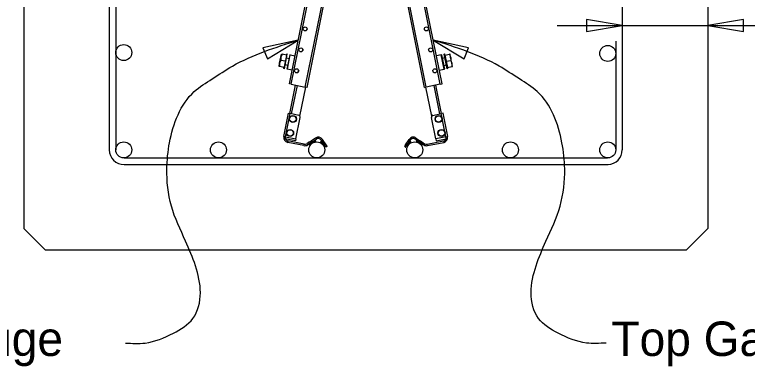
# Model space of a CAD drawing. Extents: x 0 to 36.1, y -3.7 to 15.
# Drawn here: x 2.266 to 4.409, y 2.071 to 3.1 of the extents above; entities that cross this region are included whole.
import ezdxf

# ---------------------------------------------------------------- set-up
doc = ezdxf.new("R2010")
doc.units = 0
for name, color, linetype in [('Dimension', 7, 'Continuous'), ('Leader', 7, 'Continuous'), ('Miscellaneous', 7, 'Continuous'), ('PileConc', 7, 'Continuous'), ('PrestressSteel', 7, 'Continuous')]:
    doc.layers.add(name, color=color, linetype=linetype)

msp = doc.modelspace()

# ---------------------------------------------------------------- linework, layer by layer
at = {"layer": 'Dimension'}
for p, q in [((3.8524, 3.0685), (4.043, 3.0685)), ((4.043, 3.0685), (4.293, 3.0685)), ((4.293, 3.0685), (5.1697, 3.0685))]:
    msp.add_line(p, q, dxfattribs=at)
for points in [[(4.043, 3.0685), (3.9389, 3.0861), (3.9389, 3.0508)], [(4.293, 3.0685), (4.3972, 3.0508), (4.3972, 3.0861)], [(3.0957, 3.0249), (2.9923, 3.0032), (3.0052, 2.9704)], [(3.4904, 3.0249), (3.5809, 2.9704), (3.5938, 3.0032)]]:
    msp.add_lwpolyline(points, close=True, dxfattribs=at)
at = {"layer": 'Leader'}
for points in [[(2.5903, 2.1388), (2.6477, 2.1388), (2.7303, 2.1675), (2.7877, 2.2106), (2.8093, 2.2859), (2.7949, 2.3649), (2.7662, 2.4367), (2.7246, 2.5398), (2.7114, 2.6484), (2.7193, 2.7252), (2.7913, 2.8747), (2.8439, 2.912), (2.903, 2.9492), (3.0957, 3.0249)], [(3.9958, 2.1388), (3.9383, 2.1388), (3.8558, 2.1675), (3.7983, 2.2106), (3.7768, 2.2859), (3.7912, 2.3649), (3.8199, 2.4367), (3.8615, 2.5398), (3.8747, 2.6484), (3.8668, 2.7252), (3.7947, 2.8747), (3.7422, 2.912), (3.6831, 2.9492), (3.4904, 3.0249)]]:
    msp.add_spline(points, degree=3, dxfattribs=at)
at = {"layer": 'Miscellaneous'}
for p, q in [((3.5162, 2.8971), (3.3195, 3.8739)), ((3.0699, 2.8971), (3.2126, 3.6058)), ((3.0751, 2.896), (3.1768, 3.4012)), ((3.1161, 2.8878), (3.2173, 3.3902)), ((3.1213, 2.8867), (3.2224, 3.3892)), ((3.4648, 2.8867), (3.3637, 3.3892)), ((3.47, 2.8878), (3.3688, 3.3902)), ((3.511, 2.896), (3.4093, 3.4012)), ((3.1203, 3.0546), (3.1214, 3.0597)), ((3.4658, 3.0546), (3.4647, 3.0597)), ((3.0447, 2.9753), (3.0465, 2.9843)), ((3.0481, 2.984), (3.0447, 2.9753)), ((3.0465, 2.9843), (3.0481, 2.984)), ((3.0615, 2.9813), (3.0481, 2.984)), ((3.0624, 2.9848), (3.0538, 2.9418)), ((3.055, 2.9416), (3.0636, 2.9846)), ((3.0615, 2.9813), (3.0579, 2.9633)), ((3.0611, 2.9814), (3.0624, 2.9848)), ((3.0624, 2.9848), (3.0636, 2.9846)), ((3.0713, 2.9821), (3.063, 2.9409)), ((3.0635, 2.9401), (3.0721, 2.9826)), ((3.0721, 2.9826), (3.0866, 2.9797)), ((3.108, 2.9932), (3.109, 2.9984)), ((3.4781, 2.9932), (3.4771, 2.9984)), ((3.514, 2.9826), (3.4995, 2.9797)), ((3.5226, 2.9401), (3.514, 2.9826)), ((3.5148, 2.9821), (3.5231, 2.9409)), ((3.5237, 2.9848), (3.5225, 2.9846)), ((3.5311, 2.9416), (3.5225, 2.9846)), ((3.525, 2.9814), (3.5237, 2.9848)), ((3.5237, 2.9848), (3.5323, 2.9418)), ((3.5245, 2.9813), (3.5379, 2.984)), ((3.5245, 2.9813), (3.5281, 2.9633)), ((3.5395, 2.9843), (3.5379, 2.984)), ((3.5379, 2.984), (3.5413, 2.9753)), ((3.5413, 2.9753), (3.5395, 2.9843)), ((3.0393, 2.9485), (3.0411, 2.9574)), ((3.0411, 2.9574), (3.0447, 2.9753)), ((3.0445, 2.966), (3.0411, 2.9574)), ((3.0579, 2.9633), (3.0445, 2.966)), ((3.0579, 2.9633), (3.0543, 2.9454)), ((3.0614, 2.9733), (3.0692, 2.9717)), ((3.5247, 2.9733), (3.5169, 2.9717)), ((3.5281, 2.9633), (3.5415, 2.966)), ((3.5281, 2.9633), (3.5318, 2.9454)), ((3.545, 2.9574), (3.5413, 2.9753)), ((3.5415, 2.966), (3.545, 2.9574)), ((3.5468, 2.9485), (3.545, 2.9574)), ((3.0409, 2.9481), (3.0393, 2.9485)), ((3.0543, 2.9454), (3.0409, 2.9481)), ((3.0538, 2.9418), (3.0538, 2.9455)), ((3.055, 2.9416), (3.0538, 2.9418)), ((3.0651, 2.9513), (3.0572, 2.9528)), ((3.078, 2.9372), (3.0635, 2.9401)), ((3.0956, 2.9318), (3.0966, 2.937)), ((3.4905, 2.9318), (3.4894, 2.937)), ((3.5081, 2.9372), (3.5226, 2.9401)), ((3.521, 2.9513), (3.5288, 2.9528)), ((3.5311, 2.9416), (3.5323, 2.9418)), ((3.5318, 2.9454), (3.5452, 2.9481)), ((3.5323, 2.9418), (3.5322, 2.9455)), ((3.5452, 2.9481), (3.5468, 2.9485)), ((3.0751, 2.896), (3.0699, 2.8971)), ((3.0712, 2.8104), (3.0879, 2.8934)), ((3.0751, 2.896), (3.1161, 2.8878)), ((3.511, 2.896), (3.47, 2.8878)), ((3.5149, 2.8104), (3.4982, 2.8934)), ((3.511, 2.896), (3.5162, 2.8971)), ((3.0763, 2.8093), (3.093, 2.8924)), ((3.1003, 2.8028), (3.1173, 2.8875)), ((3.1213, 2.8867), (3.1161, 2.8878)), ((3.4648, 2.8867), (3.47, 2.8878)), ((3.4858, 2.8028), (3.4687, 2.8875)), ((3.5098, 2.8093), (3.493, 2.8924)), ((3.0535, 2.7431), (3.0672, 2.8112)), ((3.0587, 2.7421), (3.0724, 2.8101)), ((3.0672, 2.8112), (3.0724, 2.8101)), ((3.0969, 2.8052), (3.0724, 2.8101)), ((3.4891, 2.8052), (3.5137, 2.8101)), ((3.5189, 2.8112), (3.5137, 2.8101)), ((3.5274, 2.7421), (3.5137, 2.8101)), ((3.5326, 2.7431), (3.5189, 2.8112)), ((3.0882, 2.7362), (3.1009, 2.7993)), ((3.4979, 2.7362), (3.4852, 2.7993)), ((3.0587, 2.7421), (3.0535, 2.7431)), ((3.5274, 2.7421), (3.5326, 2.7431)), ((3.0577, 2.7369), (3.0587, 2.7421)), ((3.0871, 2.731), (3.0577, 2.7369)), ((3.0587, 2.7421), (3.0882, 2.7362)), ((3.0656, 2.7301), (3.0648, 2.7261)), ((3.1124, 2.7166), (3.0648, 2.7261)), ((3.1132, 2.7205), (3.0656, 2.7301)), ((3.0882, 2.7362), (3.0871, 2.731)), ((3.1289, 2.7273), (3.121, 2.722)), ((3.121, 2.722), (3.1232, 2.7187)), ((3.1311, 2.7239), (3.1232, 2.7187)), ((3.1311, 2.7239), (3.1289, 2.7273)), ((3.1296, 2.7214), (3.1307, 2.7197)), ((3.1462, 2.7388), (3.133, 2.73)), ((3.133, 2.73), (3.1353, 2.7267)), ((3.1337, 2.7242), (3.1349, 2.7225)), ((3.1353, 2.7267), (3.1485, 2.7355)), ((3.136, 2.7272), (3.1367, 2.7261)), ((3.1362, 2.7258), (3.1374, 2.7241)), ((3.1379, 2.727), (3.1391, 2.7252)), ((3.1421, 2.7297), (3.1432, 2.728)), ((3.1443, 2.7327), (3.145, 2.7317)), ((3.1446, 2.7314), (3.1457, 2.7296)), ((3.1633, 2.7298), (3.1615, 2.7287)), ((3.1629, 2.7326), (3.1736, 2.7166)), ((3.163, 2.7303), (3.164, 2.731)), ((3.1649, 2.7274), (3.1632, 2.7262)), ((3.1665, 2.725), (3.1648, 2.7238)), ((3.1662, 2.7254), (3.1672, 2.7261)), ((3.1769, 2.7188), (3.1663, 2.7348)), ((3.1681, 2.7225), (3.1664, 2.7213)), ((3.4092, 2.7188), (3.4198, 2.7348)), ((3.4232, 2.7326), (3.4125, 2.7166)), ((3.418, 2.7225), (3.4197, 2.7213)), ((3.4199, 2.7254), (3.4189, 2.7261)), ((3.4196, 2.725), (3.4213, 2.7238)), ((3.4212, 2.7274), (3.4229, 2.7262)), ((3.4231, 2.7303), (3.4221, 2.731)), ((3.4228, 2.7298), (3.4246, 2.7287)), ((3.4508, 2.7267), (3.4376, 2.7355)), ((3.4398, 2.7388), (3.4531, 2.73)), ((3.4415, 2.7314), (3.4404, 2.7296)), ((3.4418, 2.7327), (3.4411, 2.7317)), ((3.444, 2.7297), (3.4428, 2.728)), ((3.4482, 2.727), (3.447, 2.7252)), ((3.4499, 2.7258), (3.4487, 2.7241)), ((3.4501, 2.7272), (3.4494, 2.7261)), ((3.4531, 2.73), (3.4508, 2.7267)), ((3.4523, 2.7242), (3.4512, 2.7225)), ((3.455, 2.7239), (3.4572, 2.7273)), ((3.455, 2.7239), (3.4629, 2.7187)), ((3.4565, 2.7214), (3.4554, 2.7197)), ((3.4572, 2.7273), (3.4651, 2.722)), ((3.4651, 2.722), (3.4629, 2.7187)), ((3.4729, 2.7205), (3.5204, 2.7301)), ((3.4737, 2.7166), (3.5212, 2.7261)), ((3.5274, 2.7421), (3.4979, 2.7362)), ((3.4979, 2.7362), (3.499, 2.731)), ((3.499, 2.731), (3.5284, 2.7369)), ((3.5204, 2.7301), (3.5212, 2.7261)), ((3.5284, 2.7369), (3.5274, 2.7421)), ((3.1124, 2.7166), (3.1132, 2.7205)), ((3.1267, 2.7195), (3.126, 2.7205)), ((3.1271, 2.7198), (3.1283, 2.718)), ((3.1693, 2.7207), (3.1676, 2.7196)), ((3.1709, 2.7183), (3.1692, 2.7172)), ((3.1725, 2.7159), (3.1708, 2.7147)), ((3.1739, 2.7161), (3.1728, 2.7154)), ((3.1736, 2.7166), (3.1769, 2.7188)), ((3.1797, 2.7146), (3.1763, 2.7124)), ((3.4064, 2.7146), (3.4097, 2.7124)), ((3.4125, 2.7166), (3.4092, 2.7188)), ((3.4122, 2.7161), (3.4132, 2.7154)), ((3.4135, 2.7159), (3.4153, 2.7147)), ((3.4152, 2.7183), (3.4169, 2.7172)), ((3.4168, 2.7207), (3.4185, 2.7196)), ((3.459, 2.7198), (3.4578, 2.718)), ((3.4594, 2.7195), (3.4601, 2.7205)), ((3.4737, 2.7166), (3.4729, 2.7205))]:
    msp.add_line(p, q, dxfattribs=at)
for points in [[(3.0411, 2.9574), (3.041, 2.9568), (3.0409, 2.9481)], [(3.0447, 2.9753), (3.0446, 2.9747), (3.0445, 2.966)], [(3.5413, 2.9753), (3.5415, 2.9747), (3.5415, 2.966)], [(3.545, 2.9574), (3.5451, 2.9568), (3.5452, 2.9481)], [(3.1289, 2.7273), (3.1289, 2.7273), (3.1292, 2.7275), (3.1296, 2.7277), (3.1301, 2.7281), (3.1307, 2.7285), (3.1314, 2.729), (3.1322, 2.7295), (3.133, 2.73)], [(3.1337, 2.7242), (3.1332, 2.7239), (3.1327, 2.7235), (3.1322, 2.7232), (3.1317, 2.7228), (3.1311, 2.7225), (3.1306, 2.7221), (3.1301, 2.7218), (3.1296, 2.7214)], [(3.1353, 2.7267), (3.1344, 2.7262), (3.1337, 2.7256), (3.1329, 2.7252), (3.1323, 2.7247), (3.1318, 2.7244), (3.1314, 2.7241), (3.1312, 2.724), (3.1311, 2.7239)], [(3.1374, 2.7241), (3.1372, 2.724), (3.1369, 2.7238), (3.1367, 2.7236), (3.1364, 2.7234), (3.136, 2.7232), (3.1357, 2.723), (3.1353, 2.7227), (3.1349, 2.7225)], [(3.1367, 2.7261), (3.1366, 2.7261), (3.1366, 2.7261), (3.1364, 2.726), (3.1362, 2.7258)], [(3.1391, 2.7252), (3.1387, 2.725), (3.1383, 2.7247), (3.138, 2.7245), (3.1376, 2.7243), (3.1374, 2.7241)], [(3.1421, 2.7297), (3.1416, 2.7294), (3.1411, 2.7291), (3.1405, 2.7287), (3.14, 2.7284), (3.1395, 2.728), (3.1389, 2.7277), (3.1384, 2.7273), (3.1379, 2.727)], [(3.1457, 2.7296), (3.1455, 2.7295), (3.1453, 2.7294), (3.145, 2.7292), (3.1447, 2.729), (3.1444, 2.7288), (3.144, 2.7285), (3.1436, 2.7283), (3.1432, 2.728)], [(3.145, 2.7317), (3.145, 2.7317), (3.1449, 2.7316), (3.1448, 2.7315), (3.1446, 2.7314)], [(3.1632, 2.7262), (3.1629, 2.7266), (3.1626, 2.727), (3.1624, 2.7273), (3.1622, 2.7277), (3.162, 2.728), (3.1618, 2.7282), (3.1617, 2.7285), (3.1615, 2.7287)], [(3.1633, 2.7298), (3.1631, 2.73), (3.163, 2.7302), (3.163, 2.7303), (3.163, 2.7303)], [(3.1664, 2.7213), (3.1661, 2.7217), (3.1659, 2.7221), (3.1656, 2.7225), (3.1654, 2.7228), (3.1652, 2.7231), (3.165, 2.7234), (3.1649, 2.7236), (3.1648, 2.7238)], [(3.1662, 2.7254), (3.1659, 2.7258), (3.1656, 2.7263), (3.1652, 2.7269), (3.1649, 2.7274)], [(3.1665, 2.725), (3.1664, 2.7252), (3.1663, 2.7253), (3.1662, 2.7254), (3.1662, 2.7254)], [(3.1676, 2.7196), (3.1674, 2.7198), (3.1673, 2.72), (3.1671, 2.7203), (3.1669, 2.7206), (3.1667, 2.7209), (3.1664, 2.7213), (3.1664, 2.7213)], [(3.1709, 2.7183), (3.1706, 2.7188), (3.1702, 2.7193), (3.1699, 2.7199), (3.1695, 2.7204), (3.1692, 2.7209), (3.1688, 2.7215), (3.1685, 2.722), (3.1681, 2.7225)], [(3.4152, 2.7183), (3.4155, 2.7188), (3.4159, 2.7193), (3.4162, 2.7199), (3.4166, 2.7204), (3.4169, 2.7209), (3.4173, 2.7215), (3.4176, 2.722), (3.418, 2.7225)], [(3.4185, 2.7196), (3.4186, 2.7198), (3.4188, 2.72), (3.419, 2.7203), (3.4192, 2.7206), (3.4194, 2.7209), (3.4196, 2.7213), (3.4197, 2.7213)], [(3.4196, 2.725), (3.4197, 2.7252), (3.4198, 2.7253), (3.4199, 2.7254), (3.4199, 2.7254)], [(3.4197, 2.7213), (3.42, 2.7217), (3.4202, 2.7221), (3.4204, 2.7225), (3.4207, 2.7228), (3.4209, 2.7231), (3.421, 2.7234), (3.4212, 2.7236), (3.4213, 2.7238)], [(3.4199, 2.7254), (3.4202, 2.7258), (3.4205, 2.7263), (3.4209, 2.7269), (3.4212, 2.7274)], [(3.4228, 2.7298), (3.423, 2.73), (3.4231, 2.7302), (3.4231, 2.7303), (3.4231, 2.7303)], [(3.4229, 2.7262), (3.4232, 2.7266), (3.4234, 2.727), (3.4237, 2.7273), (3.4239, 2.7277), (3.4241, 2.728), (3.4243, 2.7282), (3.4244, 2.7285), (3.4246, 2.7287)], [(3.4404, 2.7296), (3.4406, 2.7295), (3.4408, 2.7294), (3.4411, 2.7292), (3.4414, 2.729), (3.4417, 2.7288), (3.4421, 2.7285), (3.4424, 2.7283), (3.4428, 2.728)], [(3.4411, 2.7317), (3.4411, 2.7317), (3.4412, 2.7316), (3.4413, 2.7315), (3.4415, 2.7314)], [(3.444, 2.7297), (3.4445, 2.7294), (3.445, 2.7291), (3.4455, 2.7287), (3.4461, 2.7284), (3.4466, 2.728), (3.4471, 2.7277), (3.4477, 2.7273), (3.4482, 2.727)], [(3.447, 2.7252), (3.4474, 2.725), (3.4478, 2.7247), (3.4481, 2.7245), (3.4485, 2.7243), (3.4487, 2.7241)], [(3.4487, 2.7241), (3.4489, 2.724), (3.4492, 2.7238), (3.4494, 2.7236), (3.4497, 2.7234), (3.4501, 2.7232), (3.4504, 2.723), (3.4508, 2.7227), (3.4512, 2.7225)], [(3.4494, 2.7261), (3.4494, 2.7261), (3.4495, 2.7261), (3.4497, 2.726), (3.4499, 2.7258)], [(3.4508, 2.7267), (3.4516, 2.7262), (3.4524, 2.7256), (3.4531, 2.7252), (3.4538, 2.7247), (3.4543, 2.7244), (3.4547, 2.7241), (3.4549, 2.724), (3.455, 2.7239)], [(3.4523, 2.7242), (3.4528, 2.7239), (3.4534, 2.7235), (3.4539, 2.7232), (3.4544, 2.7228), (3.455, 2.7225), (3.4555, 2.7221), (3.456, 2.7218), (3.4565, 2.7214)], [(3.4572, 2.7273), (3.4571, 2.7273), (3.4569, 2.7275), (3.4565, 2.7277), (3.456, 2.7281), (3.4554, 2.7285), (3.4546, 2.729), (3.4539, 2.7295), (3.4531, 2.73)], [(3.1271, 2.7198), (3.1269, 2.7197), (3.1268, 2.7196), (3.1267, 2.7195), (3.1267, 2.7195)], [(3.1307, 2.7197), (3.1303, 2.7194), (3.13, 2.7192), (3.1296, 2.7189), (3.1293, 2.7187), (3.129, 2.7185), (3.1287, 2.7183), (3.1285, 2.7182), (3.1283, 2.718)], [(3.1708, 2.7147), (3.1707, 2.7149), (3.1705, 2.7151), (3.1703, 2.7154), (3.1701, 2.7157), (3.1699, 2.716), (3.1697, 2.7164), (3.1694, 2.7168), (3.1692, 2.7172)], [(3.1728, 2.7154), (3.1728, 2.7154), (3.1728, 2.7155), (3.1727, 2.7157), (3.1725, 2.7159)], [(3.1763, 2.7124), (3.1763, 2.7125), (3.1761, 2.7127), (3.1759, 2.7131), (3.1755, 2.7136), (3.1751, 2.7143), (3.1746, 2.715), (3.1741, 2.7158), (3.1736, 2.7166)], [(3.1769, 2.7188), (3.1774, 2.718), (3.178, 2.7172), (3.1784, 2.7165), (3.1789, 2.7159), (3.1792, 2.7153), (3.1795, 2.7149), (3.1796, 2.7147), (3.1797, 2.7146)], [(3.4092, 2.7188), (3.4086, 2.718), (3.4081, 2.7172), (3.4076, 2.7165), (3.4072, 2.7159), (3.4069, 2.7153), (3.4066, 2.7149), (3.4065, 2.7147), (3.4064, 2.7146)], [(3.4097, 2.7124), (3.4098, 2.7125), (3.41, 2.7127), (3.4102, 2.7131), (3.4106, 2.7136), (3.411, 2.7143), (3.4115, 2.715), (3.412, 2.7158), (3.4125, 2.7166)], [(3.4132, 2.7154), (3.4133, 2.7154), (3.4133, 2.7155), (3.4134, 2.7157), (3.4135, 2.7159)], [(3.4153, 2.7147), (3.4154, 2.7149), (3.4156, 2.7151), (3.4158, 2.7154), (3.4159, 2.7157), (3.4162, 2.716), (3.4164, 2.7164), (3.4167, 2.7168), (3.4169, 2.7172)], [(3.4554, 2.7197), (3.4557, 2.7194), (3.4561, 2.7192), (3.4565, 2.7189), (3.4568, 2.7187), (3.4571, 2.7185), (3.4574, 2.7183), (3.4576, 2.7182), (3.4578, 2.718)], [(3.459, 2.7198), (3.4592, 2.7197), (3.4593, 2.7196), (3.4594, 2.7195), (3.4594, 2.7195)]]:
    msp.add_lwpolyline(points, dxfattribs=at)
for centre, radius in [((3.1157, 3.0582), 0.00589), ((3.4704, 3.0582), 0.00589), ((3.1033, 2.9968), 0.00589), ((3.4828, 2.9968), 0.00589), ((3.091, 2.9354), 0.00589), ((3.4951, 2.9354), 0.00589), ((3.08, 2.7945), 0.0104), ((3.08, 2.7945), 0.00951), ((3.5061, 2.7945), 0.0104), ((3.5061, 2.7945), 0.00951), ((3.0717, 2.7536), 0.0104), ((3.0717, 2.7536), 0.00951), ((3.5144, 2.7536), 0.0104), ((3.5144, 2.7536), 0.00951)]:
    msp.add_circle(centre, radius, dxfattribs=at)
for centre, radius, start, end in [((3.072, 2.982), 0.000668, 78.6185, 168.6185), ((3.5141, 2.982), 0.000668, 11.3815, 101.3815), ((3.0636, 2.9407), 0.000668, 168.6185, 258.6185), ((3.5224, 2.9407), 0.000668, 281.3815, 11.3815), ((3.096, 2.8003), 0.00501, 348.6185, 78.6185), ((3.4901, 2.8003), 0.00501, 101.3815, 191.3815), ((3.0677, 2.7403), 0.0144, 168.6185, 258.6185), ((3.5184, 2.7403), 0.0144, 281.3815, 11.3815), ((3.0677, 2.7403), 0.0104, 168.6185, 196.9761), ((3.0677, 2.7403), 0.0104, 198.8835, 258.6185), ((3.1152, 2.7307), 0.0104, 258.6185, 303.6185), ((3.1542, 2.7268), 0.0144, 33.6185, 123.6185), ((3.1542, 2.7268), 0.0104, 33.6185, 123.6185), ((3.4318, 2.7268), 0.0144, 56.3815, 146.3815), ((3.4318, 2.7268), 0.0104, 56.3815, 146.3815), ((3.4709, 2.7307), 0.0104, 236.3815, 281.3815), ((3.5184, 2.7403), 0.0104, 281.3815, 341.1165), ((3.5184, 2.7403), 0.0104, 343.0239, 11.3815), ((3.1152, 2.7307), 0.0144, 258.6185, 303.6185), ((3.4709, 2.7307), 0.0144, 236.3815, 281.3815)]:
    msp.add_arc(centre, radius, start, end, dxfattribs=at)
at = {"layer": 'PileConc'}
for p, q in [((2.293, 4.3493), (2.293, 2.4743)), ((4.293, 4.3493), (4.293, 2.4743)), ((2.3555, 2.4118), (2.293, 2.4743)), ((4.293, 2.4743), (4.2305, 2.4118)), ((2.3555, 2.4118), (4.2305, 2.4118))]:
    msp.add_line(p, q, dxfattribs=at)
at = {"layer": 'PrestressSteel'}
for p, q in [((2.543, 4.1196), (2.543, 2.704)), ((2.5618, 4.1196), (2.5618, 2.704)), ((4.043, 3.7277), (4.043, 2.704)), ((4.0242, 3.0227), (4.0242, 2.704)), ((2.5861, 2.6806), (4, 2.6806)), ((2.5862, 2.6618), (4.0017, 2.6618))]:
    msp.add_line(p, q, dxfattribs=at)
for centre in [(2.5853, 2.9888), (4.0008, 2.9863), (2.5853, 2.704), (2.8623, 2.704), (3.1497, 2.704), (3.4364, 2.704), (3.7161, 2.704), (4.0008, 2.704)]:
    msp.add_circle(centre, 0.0234, dxfattribs=at)
for centre, start, end in [((2.5853, 2.704), 180, 271.2723), ((4.0008, 2.704), 271.2723, 0)]:
    msp.add_arc(centre, 0.0423, start, end, dxfattribs=at)

# ---------------------------------------------------------------- texts
at = {"layer": 'Dimension'}
for s, p in [('Tip Gauge', (1.7783, 2.1009)), ('Top Gauge', (4.0115, 2.1009))]:
    msp.add_text(s, height=0.1008, dxfattribs=at).set_placement(p)

doc.saveas('drawing.dxf')
